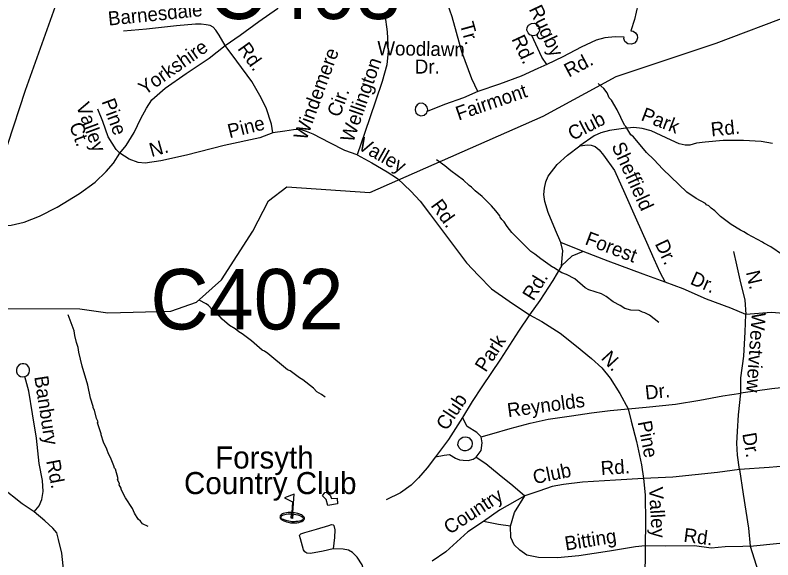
# Model space of a CAD drawing. Extents: x 1547597 to 1699558, y 810033 to 920809.
# Drawn here: x 1614133 to 1619273, y 857184 to 860880 of the extents above; entities that cross this region are included whole.
import ezdxf

# ---------------------------------------------------------------- set-up
doc = ezdxf.new("R2010")
doc.units = 0
for name, color, linetype in [('Exist Cultural Recreational Golf Course CELL', 7, 'Continuous'), ('Exist Cultural Recreational Golf Course Label', 7, 'Continuous'), ('Exist Hydrographic Creek Single Shore', 7, 'Continuous'), ('Exist Hydrographic Misc Water Feature', 7, 'Continuous'), ('Exist Road Non-System Type 51', 7, 'Continuous'), ('Exist Road Non-System Type 51 Label', 7, 'Continuous'), ('Exist Road Secondary Structure Culvert Number Label', 7, 'Continuous')]:
    doc.layers.add(name, color=color, linetype=linetype)

msp = doc.modelspace()

# ---------------------------------------------------------------- linework, layer by layer
at = {"layer": 'Exist Cultural Recreational Golf Course CELL'}
msp.add_lwpolyline([(1616025.6, 857630), (1615960.2, 857605.4), (1616014.3, 857576.7), (1616009, 857505.3), (1616016.3, 857504.8), (1616015.6, 857494.8), (1616013.4, 857464.9), (1616015.6, 857494.8), (1616025, 857493.5), (1616037.1, 857491.3), (1616049.5, 857488.7), (1616057.8, 857486.4), (1616068.7, 857482.2), (1616071.4, 857481.2), (1616080.1, 857475.8), (1616084.6, 857471.1), (1616086.5, 857467.1), (1616087.4, 857463.2), (1616087.1, 857461.5), (1616086.6, 857459.9), (1616086.1, 857458.6), (1616085.1, 857457.2), (1616080.5, 857452.7), (1616073.9, 857449.4), (1616062.7, 857446.1), (1616051.9, 857443.9), (1616037.6, 857442.7), (1616026.7, 857441.9), (1616010.6, 857442.4), (1616001.7, 857443.8), (1615990.2, 857445.2), (1615977.1, 857448), (1615963.8, 857452), (1615952.4, 857456.3), (1615944.9, 857460.2), (1615940.4, 857464.4), (1615937.3, 857469.4), (1615936.6, 857473.5), (1615938, 857477.8), (1615941.1, 857482), (1615944.8, 857485.6), (1615948.5, 857487.4), (1615953.3, 857489.3), (1615961.1, 857491.4), (1615971.7, 857493.4), (1615985, 857494.8), (1615997.9, 857495.5), (1616008.2, 857495.3), (1616009, 857505.3), (1616016.3, 857504.8), (1616013.4, 857464.9), (1616006, 857465.4), (1616008.2, 857495.3), (1616009, 857505.3), (1615992.7, 857505), (1615984.9, 857504.9), (1615972.4, 857502.9), (1615962, 857501.2), (1615950.4, 857497.6), (1615945.3, 857495.2), (1615938.7, 857491.7), (1615934.3, 857487.6), (1615931.5, 857484.5), (1615929.6, 857479.8), (1615928.9, 857475.9), (1615929.5, 857470), (1615930.4, 857467.1), (1615933.7, 857462), (1615936.8, 857458.9), (1615942, 857454.7), (1615946.5, 857452), (1615955.2, 857447.6), (1615962.6, 857445), (1615974.5, 857441.2), (1615985.5, 857438.2), (1615999.9, 857435.8), (1616009.3, 857434.7), (1616022.8, 857434.5), (1616033, 857434.7), (1616043.6, 857435.8), (1616056.6, 857437.4), (1616069.3, 857440.7), (1616077.3, 857444.1), (1616085.1, 857448), (1616089.2, 857451.7), (1616091.9, 857454.9), (1616093.1, 857457), (1616093.8, 857458.6), (1616094.5, 857461.1), (1616095.1, 857463.8), (1616094.8, 857468.3), (1616093.3, 857472.5), (1616089.7, 857477.9), (1616087.4, 857480.7), (1616081.8, 857485.1), (1616077.3, 857488.1), (1616069.3, 857492.1), (1616063.7, 857494.2), (1616050.8, 857498.6), (1616040, 857501.4), (1616016.3, 857504.8)], close=True, dxfattribs=at)
at = {"layer": 'Exist Hydrographic Creek Single Shore'}
for points in [[(1618887.7, 860689), (1619415.7, 860888.3), (1619648.8, 860886.9), (1619840.7, 860850.2), (1620232.8, 860861.9), (1620650.8, 860955.3), (1621242.8, 860949.7), (1621443.8, 861011.3), (1621679.4, 861104.8), (1622045.6, 861286.4), (1622264.9, 861672.7), (1622362.8, 861810), (1622480.8, 861932.3), (1622532.7, 862065.9), (1622577.8, 862330.8)], [(1613841.5, 859271.2), (1614203.9, 860371.1), (1614439.9, 861036.9)], [(1613652.6, 858889.6), (1614570.8, 858885.8), (1614761.8, 858858.9), (1615187.8, 858870), (1615362.7, 858932), (1615531.8, 859082.9), (1615744.7, 859413.4), (1615851.1, 859619.5), (1615975, 859714), (1616539.8, 859676.3), (1617713.7, 860194.1), (1618209.7, 860463), (1618887.7, 860689)]]:
    msp.add_lwpolyline(points, dxfattribs=at)
at = {"layer": 'Exist Hydrographic Misc Water Feature'}
for points in [[(1619338.1, 859254.4), (1619259, 859307.5), (1619211.3, 859332.2), (1619203.4, 859340.3), (1619100.2, 859393.7), (1619076.5, 859410), (1619052.6, 859420.3), (1618989.1, 859459.2), (1618918, 859514.2), (1618878.5, 859552.8), (1618854.7, 859569.1), (1618838.9, 859585.3), (1618823.1, 859593.5), (1618815.2, 859601.7), (1618751.7, 859634.5), (1618688.3, 859679.4), (1618526.5, 859833.6), (1618465.5, 859900.5), (1618416.1, 859947.1), (1618327.6, 860054.4), (1618309.9, 860068.6), (1618274.6, 860125.1), (1618266.8, 860133.2), (1618216.3, 860237.9), (1618179.2, 860302.4), (1618163.4, 860318.6), (1618147.9, 860352.8), (1618126.3, 860381.1), (1618088.2, 860415.7)], [(1618500.4, 858794.2), (1618437, 858843.1), (1618405.4, 858859.5), (1618389.4, 858863.7), (1618365.6, 858876.1), (1618309.6, 858878.8), (1618269.8, 858889.4), (1618238.1, 858909.9), (1618190.5, 858934.5), (1618143, 858971.2), (1618111.2, 858987.6), (1618023.6, 859016.8), (1617999.9, 859029.2), (1617928.7, 859090.2), (1617873.1, 859118.9), (1617841.4, 859131.4), (1617785.9, 859168.1), (1617777.9, 859170.2), (1617698.7, 859225.3), (1617659.2, 859257.9), (1617631.5, 859276.2), (1617503.2, 859404), (1617469.8, 859444.5), (1617450.3, 859476.7), (1617434.5, 859492.9), (1617422.7, 859509.1), (1617420.9, 859517.1), (1617393.3, 859551.5), (1617363.8, 859585.9), (1617300.7, 859648.8), (1617253.3, 859687.4), (1617229.6, 859711.8), (1617211.8, 859724), (1617174.3, 859760.5), (1617087.3, 859823.7), (1617047.7, 859858.3), (1616990.6, 859897.1)], [(1616234.8, 858288), (1616211, 858306.3), (1616179.3, 858324.7), (1616155.6, 858349), (1616084.5, 858406.1), (1616060.6, 858418.4), (1615997.3, 858465.3), (1615981.4, 858473.5), (1615847, 858583.3), (1615823.2, 858599.7), (1615807.3, 858605.9), (1615736.2, 858668.9), (1615672.9, 858717.7), (1615649.1, 858730), (1615625.4, 858750.4), (1615585.8, 858774.9), (1615536.4, 858817.6), (1615491, 858868.2), (1615467.4, 858884.5), (1615443.7, 858908.9), (1615427.8, 858921.1), (1615380.9, 858945.4)], [(1615035.4, 857408.9), (1614995.6, 857427.5), (1614981.9, 857445.6), (1614966.1, 857459.9), (1614942.7, 857500.2), (1614929.1, 857532.4), (1614880.2, 857605.1), (1614851, 857661.5), (1614851.1, 857669.5), (1614839.4, 857693.6), (1614839.5, 857701.6), (1614827.8, 857725.7), (1614831.9, 857733.7), (1614812.8, 857797.9), (1614807, 857806), (1614803.2, 857822.1), (1614779.9, 857878.4), (1614766.3, 857902.5), (1614754.7, 857934.7), (1614731.4, 857983), (1614716.1, 858031.3), (1614716.2, 858039.3), (1614691.2, 858113.6), (1614695.3, 858119.5), (1614683.7, 858143.7), (1614670.4, 858199.8), (1614662.6, 858216), (1614662.7, 858224), (1614643.6, 858280.2), (1614624.7, 858368.4), (1614586.6, 858496.9), (1614563.8, 858593.3), (1614560.3, 858625.3), (1614548.7, 858657.4), (1614537.4, 858705.6), (1614533.9, 858737.6), (1614491.9, 858846.5)], [(1616320.4, 857562.6), (1616253.1, 857553.1), (1616242.3, 857593.8), (1616216.9, 857617.9), (1616233.2, 857641.1), (1616245.3, 857642), (1616268.8, 857622.4), (1616278.4, 857598.9), (1616317.9, 857601.4), (1616320.4, 857562.6)]]:
    msp.add_lwpolyline(points, dxfattribs=at)
at = {"layer": 'Exist Road Non-System Type 51'}
msp.add_line((1617985, 859275.6), (1617834.2, 859337.7), dxfattribs=at)
for points in [[(1615557.3, 860673.4), (1615658.2, 860743.8), (1615785.5, 860835.8), (1615912.6, 860923.9), (1616003.7, 861008.3)], [(1617272.3, 860361.6), (1617230.6, 860448.3), (1617163.5, 860631.4), (1617127.5, 860761.8), (1617097.3, 860868), (1617065.7, 860958.3)], [(1618358, 860948.9), (1618333.5, 860849.6), (1618309.4, 860773.8), (1618325.7, 860771.1), (1618341.9, 860759.7), (1618352, 860742.9), (1618354.4, 860725.1), (1618348.6, 860705), (1618333.9, 860689.5), (1618313.7, 860681.9), (1618288.6, 860685.4), (1618269.7, 860702), (1618261.9, 860722.1), (1618264.9, 860730.5), (1618203.9, 860731.7), (1618133.9, 860724.7), (1618073.8, 860709.6), (1617973.2, 860663.2), (1617848.2, 860597.1), (1617738.6, 860544.5)], [(1616640.1, 860883.9), (1616656.1, 860765.7), (1616664.1, 860635.7), (1616654.4, 860541.8), (1616622.7, 860428.4), (1616576.6, 860295.3), (1616505, 860082.4), (1616452.7, 859931.4)], [(1615557.3, 860673.4), (1615516.3, 860743.8), (1615495.2, 860778.3), (1615475.2, 860798.5), (1615456.6, 860808.9), (1615429.5, 860815), (1615395.6, 860819.3), (1615355.5, 860818.1), (1615227.6, 860806.1), (1615023.5, 860785.3), (1614867.5, 860771.6)], [(1617637.6, 860741.8), (1617625.1, 860746.7), (1617611.9, 860759.8), (1617604.9, 860776.9), (1617607.3, 860795.9), (1617616, 860811.5), (1617634.6, 860823.7), (1617655.9, 860825.1), (1617676.1, 860815.1), (1617688.1, 860798), (1617690.1, 860776), (1617681.7, 860756.5), (1617666.6, 860744), (1617649.8, 860740.4), (1617637.6, 860741.8)], [(1617738.6, 860544.5), (1617706.4, 860595.1), (1617637.6, 860741.8)], [(1614842.9, 859942.5), (1614885.6, 859995.8), (1614941, 860082.9), (1614986.3, 860178.1), (1615023.4, 860249.6), (1615060.1, 860305), (1615151.2, 860383.6), (1615292.7, 860483.4), (1615448.1, 860586.9), (1615557.3, 860673.4)], [(1615881.8, 860080.9), (1615870.9, 860140.9), (1615834.5, 860251.3), (1615793.7, 860334), (1615737.2, 860428.8), (1615637.6, 860568.1), (1615557.3, 860673.4)], [(1617738.6, 860544.5), (1617679.3, 860517.7), (1617566.5, 860465.3), (1617418, 860411.7), (1617272.3, 860361.6)], [(1617272.3, 860361.6), (1617174.8, 860319.4), (1617046.2, 860273.4), (1616928.8, 860226.7)], [(1616928.8, 860226.7), (1616931.2, 860237.5), (1616928.1, 860255.3), (1616916.1, 860272), (1616896.5, 860281.6), (1616872.8, 860279.9), (1616859, 860270.1), (1616848.5, 860255), (1616845.5, 860237), (1616850.9, 860217.5), (1616866.8, 860202.2), (1616884.9, 860196.4), (1616907, 860200.3), (1616924.8, 860216.6), (1616928.8, 860226.7)], [(1614842.9, 859942.5), (1614817.4, 859968.8), (1614764.7, 860053.5), (1614726.4, 860158.1), (1614693.7, 860242.4)], [(1619270.8, 860009.9), (1619194, 860021.3), (1619074.3, 860029.1), (1618936.4, 860029.1), (1618814.3, 860017), (1618754.4, 860011.8), (1618710.3, 859998.5), (1618678.2, 859997.1), (1618636.4, 860005.6), (1618582.9, 860030.5), (1618515.5, 860063.4), (1618447.7, 860095), (1618386.2, 860111.3), (1618330.3, 860117.2), (1618260.3, 860111.2), (1618164.4, 860096.6), (1618106.2, 860081), (1618059.8, 860060.3), (1617964, 859993.4)], [(1615881.8, 860080.9), (1615791.5, 860048.3), (1615550.9, 859995.7), (1615294.3, 859929.7), (1615121.8, 859890.4), (1615015.6, 859875.9), (1614967.9, 859880.7), (1614906.3, 859901.5), (1614842.9, 859942.5)], [(1616452.7, 859931.4), (1616369.5, 859961.5), (1616268.5, 860013), (1616153.4, 860072.7), (1616109.7, 860089.4), (1616068, 860104.1), (1616022, 860102.6), (1615961.9, 860093.6), (1615881.8, 860080.9)], [(1617834.2, 859337.7), (1617798.5, 859420.6), (1617748.3, 859541.3), (1617725.6, 859615.6), (1617720.1, 859662.5), (1617722.8, 859705.5), (1617731.9, 859749.4), (1617748.1, 859787), (1617809.1, 859866.1), (1617880, 859929.1), (1617964, 859993.4)], [(1617964, 859993.4), (1618014.9, 859999), (1618041.5, 859996.4), (1618066.7, 859988.1), (1618094.5, 859966.7), (1618123.8, 859929.3), (1618198.1, 859826.3), (1618269.8, 859669.4), (1618349, 859490.3), (1618416.6, 859339.4), (1618464.7, 859226.6), (1618507.3, 859136.1), (1618543.3, 859067.3)], [(1613669.2, 859495.2), (1613768.9, 859466.8), (1613878.7, 859455.1), (1613984.4, 859447.6), (1614106.4, 859455.7), (1614194.6, 859474.3), (1614297.1, 859514.9), (1614417.8, 859577.1), (1614569, 859668.7), (1614676.2, 859747.1), (1614751.1, 859819.8), (1614799.9, 859875.1), (1614842.9, 859942.5)], [(1616452.7, 859931.4), (1616551.7, 859878), (1616656.5, 859816.2), (1616725.6, 859771.2), (1616818.1, 859685.6), (1616881, 859616.7), (1616951.4, 859525.5), (1617031.6, 859416.4), (1617119.4, 859298.9), (1617193.9, 859199.8), (1617276.3, 859112.4), (1617364.8, 859023), (1617483.1, 858939.1), (1617621.6, 858847.1)], [(1617839.8, 859179.6), (1617848.3, 859279.9), (1617834.2, 859337.7)], [(1617985, 859275.6), (1617909.6, 859245.1), (1617839.8, 859179.6)], [(1618543.3, 859067.3), (1618393.3, 859121.8), (1618156.8, 859211.2), (1617985, 859275.6)], [(1619006, 859276.3), (1619025.6, 859186.4), (1619053.7, 859064), (1619083.8, 858947.7), (1619089.4, 858849.3)], [(1617839.8, 859179.6), (1617779.3, 859079), (1617691.3, 858942.5), (1617621.6, 858847.1)], [(1619089.4, 858849.3), (1618987.2, 858891), (1618822.2, 858953.6), (1618665.5, 859021.8), (1618543.3, 859067.3)], [(1617621.6, 858847.1), (1617547.6, 858734.7), (1617424.9, 858544.7), (1617298.6, 858356.8), (1617232.8, 858257), (1617167.1, 858148.7)], [(1617621.6, 858847.1), (1617706.7, 858801.7), (1617829.3, 858721.6), (1617941.8, 858633.9), (1618042.2, 858550.4), (1618113.1, 858487.1), (1618169.9, 858416.3), (1618234.1, 858313.4), (1618290.4, 858208.4)], [(1619054.8, 858314.8), (1619054.8, 858418.1), (1619076, 858566), (1619084.6, 858729.8), (1619089.4, 858849.3)], [(1620156.4, 858859.2), (1620088.3, 858833.8), (1619905.3, 858804.6), (1619755.3, 858837.7), (1619580.1, 858845.5), (1619476.9, 858845.5), (1619401, 858851.4), (1619262.7, 858861.1), (1619089.4, 858849.3)], [(1614198.6, 858427.1), (1614209.5, 858431.4), (1614219.9, 858440.4), (1614227.3, 858452.1), (1614230.4, 858465.2), (1614230.2, 858476.7), (1614225.7, 858490.6), (1614216.3, 858502.6), (1614204.3, 858510.6), (1614192, 858514.1), (1614180.2, 858514.1), (1614167.9, 858510.9), (1614156.7, 858504), (1614145.5, 858490), (1614141.1, 858475.1), (1614141.5, 858460.4), (1614147.4, 858446.3), (1614156.7, 858435.1), (1614169.4, 858427.7), (1614185, 858424.7), (1614198.6, 858427.1)], [(1614260.8, 857508.7), (1614295.3, 857550.2), (1614314, 857593.9), (1614322.9, 857647.7), (1614318, 857721.7), (1614295.7, 857838), (1614276.4, 858010.1), (1614250.9, 858174.5), (1614225.2, 858328.7), (1614198.6, 858427.1)], [(1619722.6, 858369.4), (1619651.7, 858374.5), (1619415.9, 858360), (1619267, 858344), (1619054.8, 858314.8)], [(1618290.4, 858208.4), (1618412.9, 858220.1), (1618613, 858241), (1618778.3, 858268), (1618933.6, 858297.5), (1619054.8, 858314.8)], [(1619045.9, 857795.9), (1619032.3, 857893.3), (1619028.4, 857975.2), (1619032.5, 858055), (1619040.1, 858166.7), (1619054.8, 858314.8)], [(1617295.2, 858019), (1617367.4, 858039.8), (1617491.8, 858075.9), (1617626.2, 858110), (1617748.4, 858138.1), (1617906.6, 858159.7), (1618042.7, 858181.6), (1618168.9, 858197.8), (1618290.4, 858208.4)], [(1618290.4, 858208.4), (1618310.9, 858124.1), (1618348.7, 857985.7), (1618381.9, 857829.1), (1618396.4, 857735)], [(1617167.1, 858148.7), (1617073.1, 858000.3), (1616983.5, 857883.7)], [(1617295.2, 858019), (1617265.5, 858047.5), (1617198.3, 858088.4), (1617167.1, 858148.7)], [(1617146.9, 857999.2), (1617157.9, 858010), (1617169.9, 858016.2), (1617184.7, 858018.3), (1617198.7, 858016.6), (1617211.6, 858010.7), (1617222.2, 858000.9), (1617229.8, 857989.4), (1617234, 857972.3), (1617231.5, 857955.7), (1617220.5, 857937.7), (1617206.3, 857926.8), (1617191, 857922.5), (1617175.6, 857922.8), (1617158.5, 857930), (1617144.2, 857944.5), (1617136.8, 857964.2), (1617139.5, 857987.4), (1617146.9, 857999.2)], [(1617261.1, 857879.5), (1617295.1, 857926.2), (1617302, 857977.9), (1617295.2, 858019)], [(1616983.5, 857883.7), (1616928.3, 857808.6), (1616869.3, 857739.5), (1616818.7, 857690.3), (1616746, 857637.4), (1616649.4, 857590.9)], [(1616983.5, 857883.7), (1617043.5, 857892.9), (1617079.6, 857898.3), (1617119.1, 857873.7), (1617146.9, 857861.4), (1617170.9, 857858.9), (1617206.9, 857858.3), (1617238.9, 857867.9), (1617261.1, 857879.5)], [(1617261.1, 857879.5), (1617326.3, 857838.5), (1617417.1, 857763.2), (1617510, 857687.9), (1617591.2, 857618.2)], [(1614260.8, 857508.7), (1614179.7, 857563.8), (1614037.5, 857675.9), (1613905.2, 857771.9), (1613837.7, 857808.8), (1613790.1, 857831.6), (1613732.2, 857838.4), (1613632.6, 857851.8)], [(1619840.4, 857703.5), (1619743.1, 857745.1), (1619628.1, 857794.8), (1619578.4, 857809.6), (1619528.8, 857822.4), (1619456.9, 857827.7), (1619248.8, 857811.1), (1619045.9, 857795.9)], [(1619045.9, 857795.9), (1618896.5, 857776.8), (1618594.3, 857745.7), (1618396.4, 857735)], [(1619045.9, 857795.9), (1619071.2, 857628.3), (1619108.2, 857398.3), (1619119.9, 857276.6)], [(1618396.4, 857735), (1618206.5, 857724), (1617980.5, 857709.8), (1617852.3, 857694), (1617776.2, 857681.1), (1617685.7, 857650.7), (1617591.2, 857618.2)], [(1618396.4, 857735), (1618406.6, 857625.5), (1618409.8, 857435.5), (1618407.4, 857277.7)], [(1617591.2, 857618.2), (1617418, 857521.1), (1617310.7, 857442.8)], [(1617492.4, 857411.3), (1617521.1, 857504.2), (1617591.2, 857618.2)], [(1614466.7, 856993.8), (1614466, 857077.9), (1614450.2, 857228.1), (1614427.7, 857322.4), (1614414.4, 857366.5), (1614388.9, 857398.8), (1614333.8, 857447.6), (1614260.8, 857508.7)], [(1617310.7, 857442.8), (1617203.7, 857374.5), (1617053.6, 857239.1), (1616960.7, 857174.8)], [(1617492.4, 857411.3), (1617412.6, 857424.5), (1617310.7, 857442.8)], [(1616290.6, 857258.4), (1616222.4, 857241.6), (1616136.5, 857226.7), (1616112.5, 857229.2), (1616098.7, 857237.3), (1616088.8, 857251.5), (1616068.1, 857325.7), (1616062.3, 857347.9), (1616064.3, 857354.4), (1616070.6, 857359.7), (1616098.6, 857369.3), (1616176.9, 857392.2), (1616261.2, 857416.9), (1616279.1, 857422.5), (1616289.1, 857421.9), (1616295, 857416.4), (1616300.7, 857388.3), (1616299.8, 857334.2), (1616290.6, 857258.4)], [(1618407.4, 857277.7), (1618341.4, 857272.8), (1618165.1, 857243.4), (1617956.8, 857210.6), (1617812.8, 857196.7), (1617683, 857200.5), (1617604.5, 857215.9), (1617555.7, 857248.5), (1617518.4, 857285.1), (1617496.4, 857336), (1617492.4, 857411.3)], [(1619119.9, 857276.6), (1619320.8, 857296.2), (1619459.1, 857324), (1619509.1, 857333.2), (1619567, 857330.4), (1619702.2, 857286.4), (1619837.4, 857240.5)], [(1616506.7, 857030.1), (1616505.9, 857087.3), (1616486.9, 857149.6), (1616453.8, 857202.1), (1616422.2, 857232.5), (1616394.5, 857248.9), (1616358.6, 857255.4), (1616290.6, 857258.4)], [(1618407.4, 857277.7), (1618405.8, 857169.9), (1618395.6, 857026), (1618383.3, 856880.3), (1618352.8, 856710.9), (1618328.7, 856569.3), (1618309.3, 856467.6)], [(1619119.9, 857276.6), (1619069.3, 857274.7), (1618950.5, 857270.8), (1618855.1, 857263), (1618742.2, 857278.6), (1618545.2, 857275.7), (1618407.4, 857277.7)], [(1619119.9, 857276.6), (1619172.5, 857105.1), (1619186.1, 857036.9), (1619211.9, 856970)]]:
    msp.add_lwpolyline(points, dxfattribs=at)

# ---------------------------------------------------------------- texts
at = {"layer": 'Exist Cultural Recreational Golf Course Label'}
for s, p in [('Forsyth', (1615489.3, 857803.2)), ('Country Club', (1615278.1, 857629.5))]:
    msp.add_text(s, height=150, rotation=0, dxfattribs=at).set_placement(p)
at = {"layer": 'Exist Road Non-System Type 51 Label'}
for s, rotation, p in [('Barnesdale', 5.8382, (1614767.5, 860808.6)), ('Rugby', 295.1496, (1617615.5, 860921)), ('Tr.', 285.4226, (1617148.7, 860820.2)), ('Rd.', 295.1496, (1617498.4, 860717.9)), ('Yorkshire', 35.1919, (1615011.7, 860333)), ('Rd.', 305.5733, (1615637.8, 860652.4)), ('Woodlawn', 359.1727, (1616589.1, 860608.5)), ('Windemere', 69.9188, (1616107.7, 860025.1)), ('Wellington', 70.8917, (1616425.8, 860010.4)), ('Dr.', 359.824, (1616843.8, 860483.5)), ('Rd.', 27.8695, (1617888.8, 860455.4)), ('Fairmont', 18.9678, (1617140.8, 860163.9)), ('Cir.', 69.9188, (1616334.6, 860181.5)), ('Valley', 290.1029, (1614544.1, 860266.9)), ('Pine', 290.1029, (1614717.2, 860294.3)), ('Park', 339.0184, (1618372.2, 860168.2)), ('Pine', 13.9339, (1615587.1, 860044.1)), ('Club', 27.4291, (1617913.6, 860025.8)), ('Rd.', 5.6725, (1618856.5, 860056.7)), ('Ct.', 290.1029, (1614497.6, 860132.7)), ('N.', 15.8077, (1615057.9, 859916.1)), ('Valley', 330.5572, (1616448.3, 859975.2)), ('Sheffield', 294.5405, (1618176.4, 859992.3)), ('Rd.', 305.8208, (1616947.9, 859587.6)), ('Forest', 339.2841, (1617992.1, 859326.1)), ('Dr.', 295.1967, (1618471, 859328.9)), ('Dr.', 336.4753, (1618705.7, 859058)), ('N.', 282.9402, (1619089.3, 859135.8)), ('Rd.', 58.4082, (1617648.5, 858935.6)), ('Westview', 265.9076, (1619130.9, 858865.1)), ('Park', 57.1847, (1617324.3, 858451.5)), ('N.', 312.4532, (1618102.3, 858549.1)), ('Banbury', 278.8092, (1614261.8, 858425.6)), ('Dr.', 5.9764, (1618410.6, 858271)), ('Club', 56.6611, (1617060.4, 858054.4)), ('Reynolds', 7.7813, (1617477.5, 858150.8)), ('Pine', 280.8136, (1618355.4, 858119)), ('Dr.', 279.8371, (1619065, 858039.1)), ('Rd.', 280.8311, (1614342.6, 857855)), ('Rd.', 4.2943, (1618108.6, 857757.4)), ('Club', 11.5111, (1617655.3, 857696.7)), ('Country', 33.1889, (1617079.7, 857352.6)), ('Valley', 273.2965, (1618432.1, 857676.1)), ('Rd.', 352.6418, (1618663.4, 857306.5)), ('Bitting', 8.9433, (1617868.6, 857246.5))]:
    msp.add_text(s, height=95, rotation=rotation, dxfattribs=at).set_placement(p)
at = {"layer": 'Exist Road Secondary Structure Culvert Number Label'}
for s, p in [('C403', (1615439.3, 860853.3)), ('C402', (1615049.7, 858747.2))]:
    msp.add_text(s, height=410.1, dxfattribs=at).set_placement(p)

doc.saveas('drawing.dxf')
